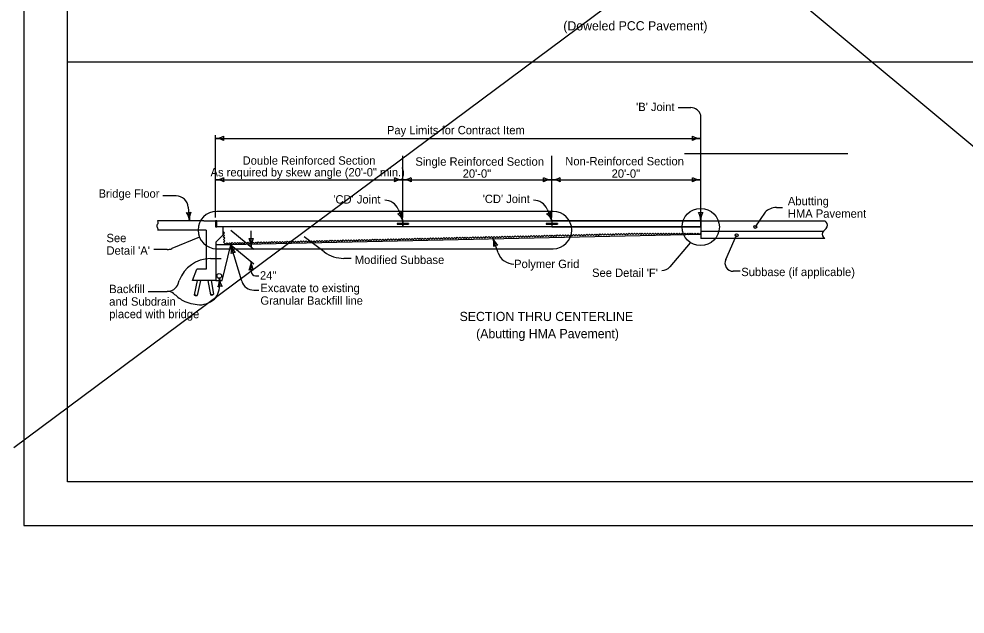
# Model space of a CAD drawing. Extents: x 8925 to 81668, y 4369 to 11918.
# Drawn here: x 13587 to 15851, y 4408 to 5831 of the extents above; entities that cross this region are included whole.
import ezdxf

# ---------------------------------------------------------------- set-up
doc = ezdxf.new("R2010")
doc.units = 0
for name, color, linetype in [('dsnNonPlotable', 7, 'Continuous'), ('dsnShtPlotShapeBatchPrint', 7, 'Continuous'), ('dsnStdBlock', 7, 'Continuous'), ('dsnStdBlockNotModified', 7, 'Continuous'), ('dsnStdBorder', 7, 'Continuous'), ('Level 5', 7, 'Continuous'), ('SheetBorder', 7, 'Continuous')]:
    doc.layers.add(name, color=color, linetype=linetype)

msp = doc.modelspace()

# ---------------------------------------------------------------- linework, layer by layer
at = {"layer": 'dsnNonPlotable'}
msp.add_line((13703, 5728.9), (16838, 5728.9), dxfattribs=at)
at = {"layer": 'dsnShtPlotShapeBatchPrint'}
for p, q in [((14059.9, 5333.7), (14059.9, 5348.5)), ((14059.9, 5348.5), (14505.4, 5348.5)), ((14059.9, 5333.7), (14059.9, 5348.5)), ((14505.4, 5348.5), (14505.4, 5342)), ((14505.4, 5342), (14505.4, 5348.5)), ((14505.4, 5342), (14505.4, 5348.5)), ((14505.4, 5348.5), (14861.8, 5348.5)), ((14861.8, 5348.5), (14861.8, 5342)), ((14075.2, 5333.7), (14059.9, 5333.7)), ((14097.1, 5333.6), (14075.2, 5333.7)), ((14505.4, 5333.6), (14097.1, 5333.6)), ((14505.4, 5342), (14492.1, 5342)), ((14492.1, 5342), (14492.1, 5340.1)), ((14492.1, 5342), (14492.1, 5340.1)), ((14518.8, 5342), (14492.1, 5342)), ((14492.1, 5342), (14505.4, 5342)), ((14492.1, 5340.1), (14505.4, 5340.1)), ((14518.8, 5342), (14505.4, 5342)), ((14505.4, 5340.1), (14505.4, 5333.6)), ((14505.4, 5333.6), (14505.4, 5340.1)), ((14505.4, 5340.1), (14518.8, 5340.1)), ((14861.8, 5333.6), (14505.4, 5333.6)), ((14518.8, 5340.1), (14518.8, 5342)), ((14848.5, 5342), (14848.5, 5340.1)), ((14861.8, 5342), (14848.5, 5342)), ((14848.5, 5342), (14848.5, 5340.1)), ((14848.5, 5340.1), (14861.8, 5340.1)), ((14875.2, 5342), (14861.8, 5342)), ((14861.8, 5340.1), (14861.8, 5333.6)), ((14044.8, 5257.9), (14070.5, 5257.9)), ((13967.5, 5197.8), (13970.2, 5205.4)), ((13895.7, 5179.4), (13941.4, 5179.4))]:
    msp.add_line(p, q, dxfattribs=at)
for centre, radius, start, end in [((13996.1, 5199.8), 71.3, 330.5092, 2.0511), ((14067.8, 5294.8), 163.6, 227.1442, 236.9942), ((14018.2, 5202.4), 55, 270.3325, 316.7198), ((14027.7, 5265.5), 118.5, 245.5915, 265.546)]:
    msp.add_arc(centre, radius, start, end, dxfattribs=at)
at = {"layer": 'dsnStdBlock'}
msp.add_lwpolyline([(13703, 6733.9), (16838, 6733.9), (16838, 4723.9), (13703, 4723.9)], close=True, dxfattribs=at)
at = {"layer": 'dsnStdBlockNotModified'}
msp.add_lwpolyline([(13598.5, 4619.4), (16942.5, 4619.4), (16942.5, 7203.4), (13598.5, 7203.4)], close=True, dxfattribs=at)
at = {"layer": 'dsnStdBorder'}
for p, q in [((15163.9, 5619.1), (15194.3, 5619.1)), ((15218.2, 5348.5), (15218.2, 5600.7)), ((14057, 5355.9), (14057, 5552.9)), ((14057, 5545.5), (15218.2, 5545.5)), ((14505.4, 5355.9), (14505.4, 5503.5)), ((14861.8, 5355.9), (14861.8, 5503.5)), ((15179.7, 5509), (15570.6, 5509)), ((14057, 5446.5), (14505.4, 5446.5)), ((14505.4, 5446.5), (14861.8, 5446.5)), ((14861.8, 5446.5), (15218.2, 5446.5)), ((13962.7, 5408.1), (13930.9, 5408.1)), ((13991.8, 5381), (13994.6, 5348.5)), ((14865, 5370.8), (14059.9, 5370.8)), ((14493.9, 5376.2), (14505.4, 5348.5)), ((14850.3, 5376.2), (14861.8, 5348.5)), ((15372.3, 5369.4), (15348.6, 5333.9)), ((15399.3, 5380), (15414.1, 5380)), ((14028.7, 5348.5), (13918.1, 5348.5)), ((14028.7, 5348.5), (14057, 5348.5)), ((14057, 5348.5), (14057, 5333.7)), ((14059.9, 5348.5), (14057, 5348.5)), ((14057, 5345.1), (14059.9, 5348.1)), ((14057, 5347.2), (14057.8, 5348.1)), ((14059.9, 5348.1), (14057, 5348.1)), ((14057, 5343), (14059.9, 5346)), ((14057, 5340.9), (14059.9, 5343.9)), ((14059.9, 5348.5), (15218.2, 5348.5)), ((14505.4, 5333.6), (14505.4, 5348.5)), ((15218.2, 5348.5), (14861.8, 5348.5)), ((14861.8, 5348.5), (14861.8, 5342)), ((14861.8, 5348.5), (14861.8, 5333.6)), ((15218.2, 5333.6), (15218.2, 5348.5)), ((15218.2, 5348.5), (15515, 5348.5)), ((15218.2, 5348.5), (15218.2, 5333.6)), ((15518.2, 5345.4), (15515, 5348.5)), ((14034.7, 5325.6), (13918.1, 5325.6)), ((14034.7, 5325.6), (14034.7, 5232.7)), ((14057, 5338.8), (14059.9, 5341.8)), ((14057, 5336.7), (14059.9, 5339.7)), ((14057, 5334.6), (14059.9, 5337.6)), ((14057, 5333.7), (14059.9, 5333.7)), ((14058.1, 5333.7), (14059.9, 5335.5)), ((15218.2, 5333.6), (14059.9, 5333.6)), ((14074.8, 5333.7), (14074.8, 5314.3)), ((14093.6, 5325.9), (14148.9, 5280.8)), ((14142.4, 5286.1), (14142.4, 5324.3)), ((14492.1, 5342), (14518.8, 5342)), ((14492.1, 5340.1), (14518.8, 5340.1)), ((14492.1, 5340.1), (14518.8, 5340.1)), ((14518.8, 5342), (14518.8, 5340.1)), ((14848.5, 5342), (14875.2, 5342)), ((14848.5, 5340.1), (14875.2, 5340.1)), ((14861.8, 5342), (14875.2, 5342)), ((14875.2, 5340.1), (14861.8, 5340.1)), ((14861.8, 5340.1), (14861.8, 5333.6)), ((14861.8, 5333.6), (15218.2, 5333.6)), ((14875.2, 5342), (14875.2, 5340.1)), ((14875.2, 5342), (14875.2, 5340.1)), ((15218.2, 5333.6), (15218.2, 5305.9)), ((15218.2, 5323.7), (15511.7, 5323.7)), ((15511.9, 5324), (15518.2, 5330.2)), ((14018.8, 5309.2), (13952.6, 5281.9)), ((14074.8, 5314.3), (14058, 5297.5)), ((15218.2, 5316), (14093.6, 5290.6)), ((14317.2, 5274.1), (14269.2, 5309.7)), ((14733.4, 5271.5), (14720.9, 5307.5)), ((15514.8, 5305.9), (15218.2, 5305.9)), ((15277.9, 5255.6), (15304.1, 5313.9)), ((15515, 5305.7), (15511.9, 5308.9)), ((13941.2, 5279.6), (13909.7, 5279.6)), ((14058, 5297.5), (14058, 5205.9)), ((14093.6, 5290.6), (14058, 5290.6)), ((14059.9, 5281.7), (14865, 5281.7)), ((14072.9, 5205.9), (14093.6, 5290.6)), ((14093.6, 5290.6), (14148.9, 5245.6)), ((14120.1, 5203.7), (14093.6, 5290.6)), ((15192.7, 5295.5), (15144.1, 5238.4)), ((14381.3, 5258.5), (14364.4, 5258.5)), ((14002, 5205.9), (14012.3, 5232.7)), ((14034.7, 5232.7), (14012.3, 5232.7)), ((14142.4, 5226.8), (14142.4, 5250.8)), ((14152.4, 5216.8), (14160.9, 5216.8)), ((15312.2, 5227.6), (15296, 5227.6)), ((14058, 5205.9), (14002, 5205.9)), ((14013.5, 5205.9), (14006, 5171.1)), ((14021.1, 5205.9), (14013.2, 5169.5)), ((14038.7, 5205.9), (14045, 5171.6)), ((14046.3, 5205.9), (14052.4, 5172.9)), ((14058, 5205.9), (14072.9, 5205.9)), ((14148.5, 5182.7), (14160.9, 5182.7))]:
    msp.add_line(p, q, dxfattribs=at)
for points in [[(14077.8, 5295.5), (14076, 5297.2), (14079.1, 5300.4), (14075.9, 5303.5), (14079, 5306.8), (14075.7, 5309.8), (14078.8, 5313.1), (14075.6, 5316.2), (14078.7, 5319.4), (14075.4, 5322.5), (14075.6, 5322.7)], [(14136.2, 5295.6), (14137.8, 5294), (14140.9, 5297.3), (14144.2, 5294.2), (14147.3, 5297.4), (14150.5, 5294.3), (14153.6, 5297.6), (14156.8, 5294.5), (14159.9, 5297.7), (14163.2, 5294.6), (14166.3, 5297.9), (14169.5, 5294.8), (14172.6, 5298), (14175.9, 5294.9), (14178.9, 5298.2), (14182.2, 5295.1), (14185.3, 5298.3), (14188.5, 5295.2), (14191.6, 5298.5), (14194.9, 5295.4), (14197.9, 5298.6), (14201.2, 5295.5), (14204.3, 5298.8), (14207.5, 5295.7), (14210.6, 5298.9), (14212.2, 5297.4)], [(14212.2, 5297.4), (14213.9, 5295.8), (14217, 5299.1), (14220.2, 5296), (14223.3, 5299.2), (14226.5, 5296.1), (14229.6, 5299.4), (14232.9, 5296.3), (14236, 5299.5), (14239.2, 5296.4), (14242.3, 5299.7), (14245.5, 5296.6), (14248.6, 5299.8), (14251.9, 5296.7), (14255, 5300), (14258.2, 5296.9), (14261.3, 5300.1), (14264.5, 5297), (14267.6, 5300.2), (14270.9, 5297.2), (14274, 5300.4), (14277.2, 5297.3), (14280.3, 5300.5), (14283.5, 5297.5), (14286.6, 5300.7), (14288.2, 5299.1)], [(14288.2, 5299.2), (14289.9, 5297.6), (14293, 5300.8), (14296.2, 5297.8), (14299.3, 5301), (14302.5, 5297.9), (14305.6, 5301.1), (14308.9, 5298.1), (14312, 5301.3), (14315.2, 5298.2), (14318.3, 5301.4), (14321.5, 5298.3), (14324.6, 5301.6), (14327.9, 5298.5), (14331, 5301.7), (14334.2, 5298.6), (14337.3, 5301.9), (14340.5, 5298.8), (14343.6, 5302), (14346.9, 5298.9), (14350, 5302.2), (14353.2, 5299.1), (14356.3, 5302.3), (14359.5, 5299.2), (14362.6, 5302.5), (14364.3, 5300.9)], [(14364.3, 5300.9), (14365.9, 5299.4), (14369, 5302.6), (14372.2, 5299.5), (14375.3, 5302.8), (14378.5, 5299.7), (14381.6, 5302.9), (14384.9, 5299.8), (14388, 5303.1), (14391.2, 5300), (14394.3, 5303.2), (14397.6, 5300.1), (14400.6, 5303.4), (14403.9, 5300.3), (14407, 5303.5), (14410.2, 5300.4), (14413.3, 5303.7), (14416.6, 5300.6), (14419.6, 5303.8), (14422.9, 5300.7), (14426, 5304), (14429.2, 5300.9), (14432.3, 5304.1), (14435.6, 5301), (14438.6, 5304.3), (14440.3, 5302.7)], [(14440.3, 5302.7), (14441.9, 5301.2), (14445, 5304.4), (14448.2, 5301.3), (14451.3, 5304.5), (14454.6, 5301.5), (14457.7, 5304.7), (14460.9, 5301.6), (14464, 5304.8), (14467.2, 5301.7), (14470.3, 5305), (14473.6, 5301.9), (14476.7, 5305.1), (14479.9, 5302), (14483, 5305.3), (14486.2, 5302.2), (14489.3, 5305.4), (14492.6, 5302.3), (14495.7, 5305.6), (14498.9, 5302.5), (14502, 5305.7), (14505.2, 5302.6), (14508.3, 5305.9), (14511.6, 5302.8), (14514.7, 5306), (14516.3, 5304.5)], [(14516.3, 5304.5), (14517.9, 5303), (14521, 5306.2), (14524.2, 5303.1), (14527.3, 5306.3), (14530.6, 5303.3), (14533.7, 5306.5), (14536.9, 5303.4), (14540, 5306.6), (14543.2, 5303.6), (14546.3, 5306.8), (14549.6, 5303.7), (14552.7, 5306.9), (14555.9, 5303.8), (14559, 5307.1), (14562.2, 5304), (14565.3, 5307.2), (14568.6, 5304.1), (14571.7, 5307.4), (14574.9, 5304.3), (14578, 5307.5), (14581.2, 5304.4), (14584.3, 5307.7), (14587.6, 5304.6), (14590.7, 5307.8), (14592.3, 5306.3)], [(14592.3, 5306.3), (14593.9, 5304.8), (14597, 5308), (14600.2, 5304.9), (14603.3, 5308.1), (14606.6, 5305), (14609.7, 5308.3), (14612.9, 5305.2), (14616, 5308.4), (14619.2, 5305.3), (14622.3, 5308.6), (14625.6, 5305.5), (14628.7, 5308.7), (14631.9, 5305.6), (14635, 5308.9), (14638.3, 5305.8), (14641.3, 5309), (14644.6, 5305.9), (14647.7, 5309.2), (14650.9, 5306.1), (14654, 5309.3), (14657.3, 5306.2), (14660.3, 5309.5), (14663.6, 5306.4), (14666.7, 5309.6), (14668.3, 5308.1)], [(14668.3, 5308), (14669.9, 5306.5), (14673, 5309.7), (14676.3, 5306.7), (14679.4, 5309.9), (14682.6, 5306.8), (14685.7, 5310), (14688.9, 5306.9), (14692, 5310.2), (14695.3, 5307.1), (14698.4, 5310.3), (14701.6, 5307.2), (14704.7, 5310.5), (14707.9, 5307.4), (14711, 5310.6), (14714.3, 5307.5), (14717.4, 5310.8), (14720.6, 5307.7), (14723.7, 5310.9), (14726.9, 5307.8), (14730, 5311.1), (14733.3, 5308), (14736.4, 5311.2), (14739.6, 5308.1), (14742.7, 5311.4), (14744.3, 5309.8)], [(14744.3, 5309.8), (14745.9, 5308.3), (14749, 5311.5), (14752.3, 5308.4), (14755.4, 5311.7), (14758.6, 5308.6), (14761.7, 5311.8), (14764.9, 5308.7), (14768, 5312), (14771.3, 5308.9), (14774.4, 5312.1), (14777.6, 5309), (14780.7, 5312.3), (14783.9, 5309.2), (14787, 5312.4), (14790.3, 5309.3), (14793.4, 5312.6), (14796.6, 5309.5), (14799.7, 5312.7), (14802.9, 5309.6), (14806, 5312.8), (14809.3, 5309.8), (14812.4, 5313), (14815.6, 5309.9), (14818.7, 5313.1), (14820.3, 5311.6)], [(14820.3, 5311.6), (14821.9, 5310), (14825, 5313.3), (14828.3, 5310.2), (14831.4, 5313.4), (14834.6, 5310.3), (14837.7, 5313.6), (14841, 5310.5), (14844, 5313.7), (14847.3, 5310.6), (14850.4, 5313.9), (14853.6, 5310.8), (14856.7, 5314), (14860, 5310.9), (14863, 5314.2), (14866.3, 5311.1), (14869.4, 5314.3), (14872.6, 5311.2), (14875.7, 5314.5), (14879, 5311.4), (14882.1, 5314.6), (14885.3, 5311.5), (14888.4, 5314.8), (14891.6, 5311.7), (14894.7, 5314.9), (14896.3, 5313.4)], [(14896.3, 5313.4), (14898, 5311.8), (14901.1, 5315.1), (14904.3, 5312), (14907.4, 5315.2), (14910.6, 5312.1), (14913.7, 5315.4), (14917, 5312.3), (14920.1, 5315.5), (14923.3, 5312.4), (14926.4, 5315.7), (14929.6, 5312.6), (14932.7, 5315.8), (14936, 5312.7), (14939.1, 5316), (14942.3, 5312.9), (14945.4, 5316.1), (14948.6, 5313), (14951.7, 5316.3), (14955, 5313.2), (14958.1, 5316.4), (14961.3, 5313.3), (14964.4, 5316.6), (14967.6, 5313.5), (14970.7, 5316.7), (14972.3, 5315.2)], [(14972.3, 5315.2), (14974, 5313.6), (14977.1, 5316.9), (14980.3, 5313.8), (14983.4, 5317), (14986.6, 5313.9), (14989.7, 5317.2), (14993, 5314.1), (14996.1, 5317.3), (14999.3, 5314.2), (15002.4, 5317.5), (15005.6, 5314.4), (15008.7, 5317.6), (15012, 5314.5), (15015.1, 5317.8), (15018.3, 5314.7), (15021.4, 5317.9), (15024.6, 5314.8), (15027.7, 5318.1), (15031, 5315), (15034.1, 5318.2), (15037.3, 5315.1), (15040.4, 5318.3), (15043.6, 5315.3), (15046.7, 5318.5), (15048.4, 5316.9)], [(15048.3, 5317.1), (15049.9, 5315.5), (15053.1, 5318.7), (15056.3, 5315.5), (15059.4, 5318.7), (15062.6, 5315.5), (15065.8, 5318.7), (15068.9, 5315.5), (15072.1, 5318.7), (15075.3, 5315.5), (15078.4, 5318.7), (15081.6, 5315.5), (15084.8, 5318.7), (15088, 5315.6), (15091.1, 5318.7), (15094.3, 5315.6), (15097.5, 5318.7), (15100.6, 5315.6), (15103.8, 5318.7), (15107, 5315.6), (15110.1, 5318.7), (15113.3, 5315.6), (15116.5, 5318.8), (15119.6, 5315.6), (15122.8, 5318.8), (15124.4, 5317.2)], [(15124.4, 5317), (15126, 5315.4), (15129.1, 5318.5), (15132.3, 5315.4), (15135.5, 5318.6), (15138.6, 5315.4), (15141.8, 5318.6), (15145, 5315.4), (15148.1, 5318.6), (15151.3, 5315.4), (15154.5, 5318.6), (15157.6, 5315.4), (15160.8, 5318.6), (15164, 5315.4), (15167.1, 5318.6), (15170.3, 5315.4), (15173.5, 5318.6), (15176.7, 5315.4), (15179.8, 5318.6), (15183, 5315.4), (15186.2, 5318.6), (15189.3, 5315.5), (15192.5, 5318.6), (15195.7, 5315.5), (15198.8, 5318.6), (15200.4, 5317.1)], [(15200.4, 5317.4), (15202, 5315.8), (15205.1, 5319), (15208.3, 5315.8), (15211.5, 5319), (15214.6, 5315.8), (15217.8, 5319), (15218.3, 5318.5)], [(14077.5, 5295.6), (14077.6, 5295.7), (14080.8, 5292.6), (14083.9, 5295.9), (14087.2, 5292.8), (14090.3, 5296), (14093.5, 5292.9), (14096.6, 5296.2), (14099.8, 5293.1), (14102.9, 5296.3), (14106.2, 5293.2), (14109.3, 5296.5), (14112.5, 5293.4), (14115.6, 5296.6), (14118.8, 5293.5), (14121.9, 5296.8), (14125.2, 5293.7), (14128.3, 5296.9), (14131.5, 5293.8), (14134.6, 5297.1), (14136.2, 5295.5)]]:
    msp.add_lwpolyline(points, dxfattribs=at)
for centre, radius in [((15218.2, 5333.6), 44.6), ((14065.9, 5216.6), 5.57)]:
    msp.add_circle(centre, radius, dxfattribs=at)
for centre, radius, start, end in [((15194.3, 5594.3), 24.8, 15.0299, 90), ((14056.4, 5588.3), 42.7, 270, 298.0725), ((14092.2, 5545.5), 16.5, 162.2666, 197.7334), ((15182.4, 5545.5), 16.5, 342.2666, 17.7333), ((15218.2, 5588.3), 42.7, 241.9275, 270), ((14056.4, 5502.8), 42.7, 61.9275, 90), ((15218.2, 5502.8), 42.7, 90, 118.0725), ((14057, 5489.3), 42.7, 270, 298.0725), ((14057, 5403.8), 42.7, 61.9275, 90), ((14092.8, 5446.5), 16.5, 162.2666, 197.7334), ((14469.6, 5446.5), 16.5, 342.2666, 17.7333), ((14505.4, 5489.3), 42.7, 241.9275, 270), ((14505.4, 5403.8), 42.7, 90, 118.0725), ((14505.4, 5489.3), 42.7, 270, 298.0725), ((14505.4, 5403.8), 42.7, 61.9275, 90), ((14541.3, 5446.5), 16.5, 162.2666, 197.7334), ((14826, 5446.5), 16.5, 342.2666, 17.7333), ((14861.8, 5489.3), 42.7, 241.9275, 270), ((14861.8, 5403.8), 42.7, 90, 118.0725), ((14861.8, 5489.3), 42.7, 270, 298.0725), ((14861.8, 5403.8), 42.7, 61.9275, 90), ((14897.7, 5446.5), 16.5, 162.2666, 197.7334), ((15182.4, 5446.5), 16.5, 342.2666, 17.7333), ((15218.2, 5489.3), 42.7, 241.9275, 270), ((15218.2, 5403.8), 42.7, 90, 118.0725), ((13962.2, 5378.4), 29.7, 4.9696, 89.1065), ((14461.9, 5362.9), 34.7, 22.5907, 90), ((14818.3, 5362.9), 34.7, 22.5907, 90), ((13991.5, 5384.2), 16.5, 257.2356, 292.7023), ((13952, 5344.8), 42.7, 4.969, 33.0415), ((14037.2, 5352.2), 42.7, 156.8965, 184.969), ((14059.9, 5326.2), 44.6, 90, 269.9998), ((14491.7, 5381.6), 16.5, 274.8595, 310.3262), ((14544.9, 5364.9), 42.7, 174.5203, 202.5928), ((14848.1, 5381.6), 16.5, 274.8572, 310.3239), ((14901.3, 5364.9), 42.7, 174.5181, 202.5905), ((14865, 5326.2), 44.6, 270.0002, 90), ((15218.2, 5384.3), 16.5, 252.2666, 287.7333), ((15175.5, 5348.5), 42.7, 360, 28.0725), ((15261, 5348.5), 42.7, 151.9275, 180), ((15399.3, 5340.4), 39.6, 90, 132.998), ((14466, 5332.1), 42.7, 22.5928, 50.6653), ((14822.4, 5332.1), 42.7, 22.5905, 50.663), ((15510.6, 5337.8), 10.7, 315, 45), ((15519.5, 5316.4), 10.7, 135, 225), ((14142.4, 5322), 16.5, 252.2666, 287.7333), ((14099.6, 5286.1), 42.7, 360, 28.0725), ((14185.1, 5286.1), 42.7, 151.9275, 180), ((14761.3, 5321.5), 42.7, 199.1779, 227.2504), ((14680.5, 5293.4), 42.7, 351.1054, 19.1779), ((13941.2, 5309.3), 29.7, 270, 292.4496), ((14134.5, 5303), 42.7, 196.9537, 225.0262), ((14052.7, 5278.1), 42.7, 348.8812, 16.9537), ((14134.5, 5303), 42.7, 196.9537, 225.0262), ((14052.7, 5278.1), 42.7, 348.8812, 16.9537), ((14732.7, 5273.6), 16.5, 91.4446, 126.9113), ((14044.8, 5178.7), 79.2, 90, 160.3012), ((14104, 5256.3), 16.5, 89.2203, 124.687), ((14104, 5256.3), 16.5, 89.2203, 124.687), ((14364.4, 5337.7), 79.2, 233.4243, 270), ((14770.8, 5284.6), 39.6, 199.1769, 270), ((15296, 5247.4), 19.8, 155.762, 270), ((14099.6, 5250.8), 42.7, 331.9275, 360), ((14142.4, 5215), 16.5, 72.2666, 107.7334), ((14185.1, 5250.8), 42.7, 180, 208.0725), ((15125.1, 5254.6), 25, 270, 319.6052), ((14023.8, 5207.2), 42.5, 337.1139, 5.1864), ((14108.5, 5214.9), 42.5, 185.1864, 213.2589), ((14152.4, 5226.8), 10, 180, 270), ((13941.4, 5207.1), 27.7, 270, 340.3019), ((14069.4, 5175.5), 16.4, 77.453, 112.9197), ((14148.5, 5212.3), 29.7, 196.9535, 270), ((13941.4, 5151.7), 27.7, 56.8248, 90)]:
    msp.add_arc(centre, radius, start, end, dxfattribs=at)
for points in [[(13918.1, 5348.5), (13919.3, 5342.5), (13916.3, 5336.5), (13919.1, 5328.9), (13918.6, 5325.6)], [(14006, 5171.1), (14009.1, 5171.5), (14010.8, 5169.8), (14013.2, 5169.5)], [(14006, 5171.1), (14008.1, 5169.6), (14010.5, 5169.8)], [(14045, 5171.6), (14047.8, 5172.7), (14050.6, 5171.5), (14052.4, 5172.9)], [(14045, 5171.6), (14047.8, 5170.7), (14049.8, 5171.5)]]:
    msp.add_spline(points, degree=3, dxfattribs=at)
at = {"layer": 'Level 5'}
for centre in [(15348.6, 5333.9), (15304.1, 5313.9)]:
    msp.add_circle(centre, 3.54, dxfattribs=at)
at = {"layer": 'SheetBorder'}
for p, q in [((13555.2, 7461.7), (17208.8, 4407.7)), ((17092.5, 7422.9), (13574.6, 4805.2))]:
    msp.add_line(p, q, dxfattribs=at)

# ---------------------------------------------------------------- texts
at = {"layer": 'dsnShtPlotShapeBatchPrint'}
for s, height, p in [('(Doweled PCC Pavement)', 22, (14889.3, 5803.8)), ("'B' Joint", 20, (15063.5, 5610.9)), ('Pay Limits for Contract Item', 20, (14467.2, 5555.3)), ('Double Reinforced Section', 20, (14121.8, 5482.6)), ('Single Reinforced Section', 20, (14535.3, 5480.1)), ('Non-Reinforced Section', 20, (14894, 5481)), ('As required by skew angle (20\'-0" min.)', 20, (14045.1, 5454.5)), ('20\'-0"', 20, (14648.5, 5451.4)), ('20\'-0"', 20, (15004.9, 5451.4)), ('Bridge Floor', 20, (13777.2, 5403.6)), ("'CD' Joint", 20, (14696.4, 5390.8)), ("'CD' Joint", 20, (14338.9, 5389.7)), ('Abutting', 20, (15426.7, 5385.7)), ('HMA Pavement', 20, (15426.7, 5355.7)), ('See', 20, (13796.1, 5297.3)), ("Detail 'A'", 20, (13796.1, 5267.3)), ('Modified Subbase', 20, (14390.3, 5245.1)), ('Polymer Grid', 20, (14771.6, 5235.3)), ("See Detail 'F'", 20, (14958.2, 5214.1)), ('Subbase (if applicable)', 20, (15315.2, 5216.1)), ('24"', 20, (14163.4, 5207.8)), ('Backfill', 20, (13802.6, 5175.4)), ('Excavate to existing', 20, (14164.4, 5177.7)), ('and Subdrain', 20, (13802.6, 5145.4)), ('Granular Backfill line', 20, (14164.4, 5147.7)), ('placed with bridge', 20, (13802.6, 5115.4)), ('(Abutting HMA Pavement)', 22, (14680.7, 5067.6))]:
    msp.add_text(s, height=height, dxfattribs=at).set_placement(p)
at = {"layer": 'dsnStdBorder'}
msp.add_text('SECTION THRU CENTERLINE', height=22, dxfattribs=at).set_placement((14641.1, 5108.6))

doc.saveas('drawing.dxf')
